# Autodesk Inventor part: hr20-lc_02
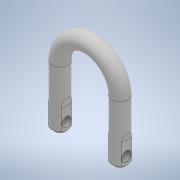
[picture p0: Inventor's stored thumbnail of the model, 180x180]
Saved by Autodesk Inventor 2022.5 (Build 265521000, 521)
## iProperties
Part Number: hr20-lc_02
Material: 一般
Document SubType Name: Modeling
Designer: ImaoCorp
Density: 1 g/cm^3
Appearance: 既定
Author: ImaoCorp
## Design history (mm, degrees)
feature "hr20-lc_02"
node "ソリッド1"
